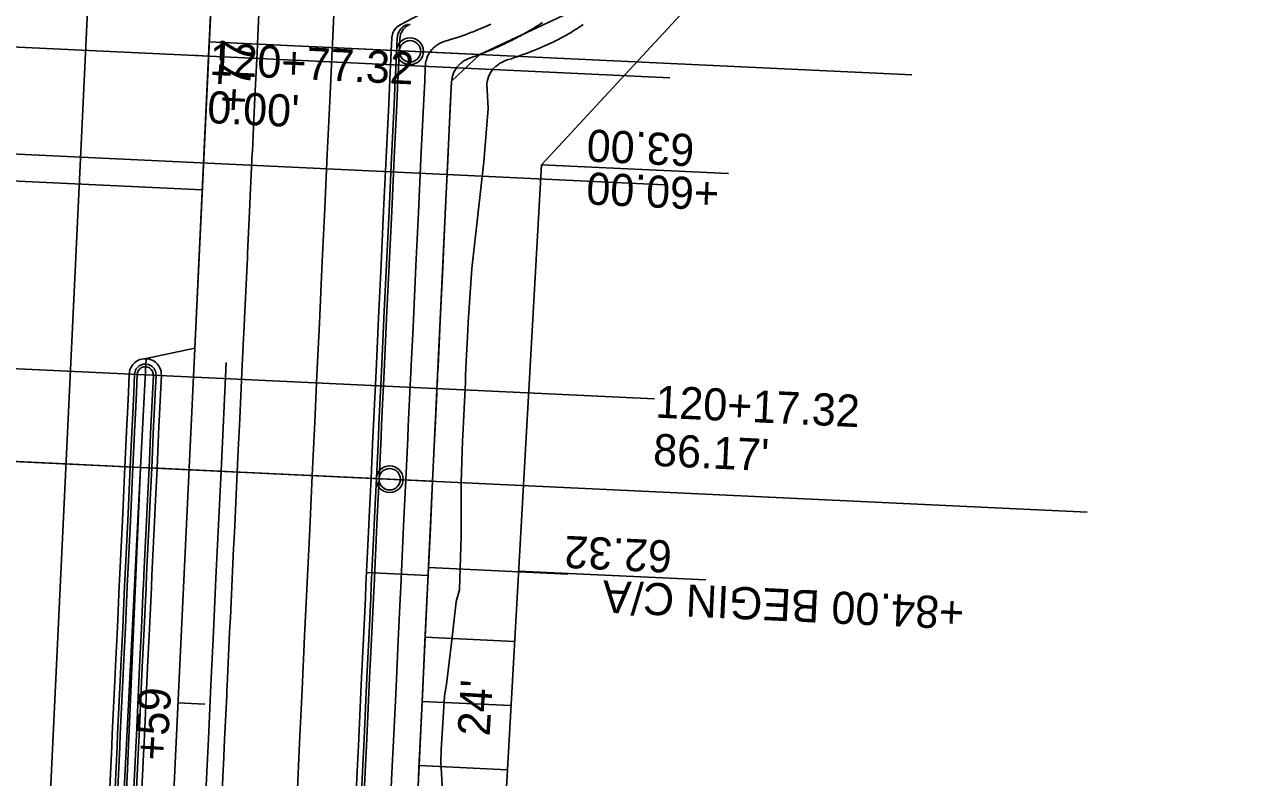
# Model space of a CAD drawing. Extents: x -70 to 701944, y -4 to 666871.
# Drawn here: x 668271.1 to 668502.1, y 655186.6 to 655327.1 of the extents above; entities that cross this region are included whole.
import ezdxf

# ---------------------------------------------------------------- set-up
doc = ezdxf.new("R2010")
doc.units = 0
for name, color, linetype in [('R_Detour', 7, 'Continuous'), ('R_Drive', 7, 'Continuous'), ('R_Horz Alg', 7, 'Continuous'), ('R_No Plot', 7, 'Continuous'), ('R_Proposed Const Limits', 7, 'Continuous'), ('R_Proposed Road', 7, 'Continuous'), ('R_ROW', 7, 'Continuous'), ('R_ROW Annot', 7, 'Continuous'), ('R_Striping', 7, 'Continuous'), ('R_Water', 7, 'Continuous'), ('T_Indications', 7, 'Continuous')]:
    doc.layers.add(name, color=color, linetype=linetype)

msp = doc.modelspace()

# ---------------------------------------------------------------- linework, layer by layer
at = {"layer": 'R_Detour'}
for p, q in [((668436.69, 655317.7), (668305.54, 655323.89)), ((668183.7, 655249.55), (668301.77, 655243.98)), ((668469.42, 655236.07), (668301.77, 655243.98))]:
    msp.add_line(p, q, dxfattribs=at)
at = {"layer": 'R_Drive'}
for p, q in [((668305.41, 655321.22), (668302.41, 655321.36)), ((668334.9, 655224.8), (668346.39, 655224.26)), ((668345.84, 655212.72), (668362.53, 655211.93)), ((668299.71, 655200.43), (668304.71, 655200.2)), ((668344.71, 655188.75), (668361.18, 655187.97))]:
    msp.add_line(p, q, dxfattribs=at)
at = {"layer": 'R_Horz Alg'}
msp.add_line((668254.91, 654251.16), (668327.61, 655791.56), dxfattribs=at)
msp.add_lwpolyline([(668294.77, 655244.31), (668308.76, 655243.65)], dxfattribs=at)
at = {"layer": 'R_No Plot'}
for p, q in [((668198.92, 655326.24), (668391.49, 655317.16)), ((668197.97, 655306.27), (668390.55, 655297.18)), ((668304.23, 655296.25), (668187.13, 655301.77)), ((668196.09, 655266.31), (668388.66, 655257.22)), ((668346.46, 655225.71), (668372.5, 655224.48)), ((668345.28, 655200.73), (668361.86, 655199.95))]:
    msp.add_line(p, q, dxfattribs=at)
for points in [[(668217.12, 655373.11), (668213.57, 655355.07), (668212.94, 655313.25), (668210.91, 655248.27), (668292.71, 655244.41), (668293.73, 655264.72), (668302.84, 655266.71), (668307.66, 655368.84)], [(668306.48, 655343.87), (668381.99, 655340.31), (668372.53, 655329.22), (668356.03, 655321.51), (668305.54, 655323.89)], [(668305.54, 655323.89), (668356.03, 655321.51), (668350.76, 655316.55), (668347.22, 655241.84), (668292.71, 655244.41), (668293.73, 655264.72), (668302.84, 655266.71)], [(668210.91, 655248.27), (668292.71, 655244.41), (668289.88, 655179.47), (668211.95, 655183.15)], [(668292.71, 655244.41), (668347.22, 655241.84), (668340.15, 655092), (668285.12, 655094.6)]]:
    msp.add_lwpolyline(points, close=True, dxfattribs=at)
for centre in [(668343.01, 655322.12), (668339.23, 655242.21)]:
    msp.add_circle(centre, 2.5, dxfattribs=at)
at = {"layer": 'R_Proposed Const Limits'}
msp.add_lwpolyline([(668349.21, 655181.68), (668348.79, 655189.43), (668348.79, 655189.45), (668348.82, 655191.7), (668349.44, 655201.69), (668349.89, 655204.36), (668349.9, 655204.45), (668350.77, 655211.63), (668351.63, 655219.29), (668351.65, 655219.39), (668352.23, 655221.58), (668352.57, 655231.57), (668352.57, 655234.26), (668352.57, 655234.35), (668352.57, 655241.58), (668352.8, 655249.39), (668352.92, 655251.58), (668352.98, 655252.9), (668353.12, 655255.42), (668353.25, 655257.94), (668353.31, 655258.89), (668353.37, 655260.47), (668353.39, 655261.57), (668353.43, 655263), (668353.78, 655270.05), (668353.86, 655271.56), (668354.56, 655281.53), (668355.69, 655291.49), (668356.82, 655301.45), (668357.62, 655311.42), (668357.37, 655316.01), (668357.41, 655316.47), (668357.51, 655316.92), (668357.65, 655317.36), (668357.84, 655317.79), (668358.07, 655318.2), (668358.34, 655318.59), (668358.53, 655318.81), (668358.66, 655318.95), (668358.99, 655319.27), (668359.01, 655319.29), (668359.39, 655319.6), (668359.57, 655319.72), (668359.81, 655319.87), (668360.25, 655320.11), (668360.33, 655320.15), (668360.7, 655320.32), (668361.16, 655320.49), (668361.38, 655320.56), (668361.93, 655320.73), (668362.54, 655320.94), (668362.76, 655321.01), (668363.21, 655321.17), (668363.59, 655321.3), (668364.34, 655321.58), (668364.53, 655321.65), (668365.37, 655321.97), (668365.91, 655322.18), (668366.11, 655322.26), (668366.76, 655322.53), (668367.31, 655322.76), (668367.45, 655322.82), (668367.76, 655322.95), (668368.12, 655323.11), (668368.32, 655323.2), (668368.33, 655323.2), (668368.98, 655323.5), (668369.1, 655323.56), (668369.13, 655323.57), (668369.84, 655323.9), (668370.17, 655324.07), (668370.47, 655324.21), (668370.52, 655324.24), (668371.14, 655324.56), (668371.22, 655324.6), (668371.71, 655324.86), (668371.9, 655324.97), (668372.2, 655325.13), (668372.28, 655325.17), (668372.62, 655325.37), (668372.96, 655325.57), (668373.26, 655325.76), (668373.3, 655325.78), (668374.32, 655326.44), (668374.54, 655326.58), (668375.33, 655327.12)], dxfattribs=at)
at = {"layer": 'R_Proposed Road'}
msp.add_line((668341.2, 655327.07), (668357.58, 655335.72), dxfattribs=at)
for points in [[(668336.55, 655259.68), (668336.62, 655261.26), (668336.67, 655262.36), (668336.74, 655263.79), (668337.07, 655270.84), (668337.15, 655272.34), (668337.62, 655282.33), (668338.09, 655292.32), (668338.56, 655302.31), (668339.03, 655312.3), (668339.25, 655316.87), (668339.27, 655317.33), (668339.29, 655317.78), (668339.31, 655318.23), (668339.33, 655318.66), (668339.35, 655319.08), (668339.37, 655319.48), (668339.38, 655319.72), (668339.39, 655319.86), (668339.4, 655320.2), (668339.4, 655320.21), (668339.42, 655320.54), (668339.43, 655320.67), (668339.43, 655320.84), (668339.45, 655321.1), (668339.45, 655321.14), (668339.46, 655321.32), (668339.47, 655321.51), (668339.47, 655321.59), (668339.48, 655321.79), (668339.49, 655322.03), (668339.49, 655322.11), (668339.5, 655322.29), (668339.51, 655322.44), (668339.52, 655322.75), (668339.53, 655322.83), (668339.54, 655323.19), (668339.56, 655323.43), (668339.56, 655323.52), (668339.57, 655323.81), (668339.59, 655324.07), (668339.59, 655324.14), (668339.6, 655324.28), (668339.6, 655324.46), (668339.61, 655324.56), (668339.61, 655324.56), (668339.64, 655324.88), (668339.65, 655324.95), (668339.66, 655324.96), (668339.75, 655325.32), (668339.81, 655325.5), (668339.87, 655325.66), (668339.89, 655325.69), (668340.07, 655326.03), (668340.1, 655326.07), (668340.3, 655326.34), (668340.4, 655326.45), (668340.57, 655326.62), (668340.62, 655326.67), (668340.87, 655326.87), (668341.2, 655327.07), (668341.55, 655327.25)], [(668337.56, 655259.63), (668337.63, 655261.21), (668337.68, 655262.31), (668337.75, 655263.74), (668338.08, 655270.79), (668338.15, 655272.3), (668338.63, 655282.29), (668339.1, 655292.27), (668339.57, 655302.26), (668340.04, 655312.25), (668340.26, 655316.82), (668340.28, 655317.28), (668340.3, 655317.73), (668340.32, 655318.18), (668340.34, 655318.61), (668340.36, 655319.03), (668340.38, 655319.43), (668340.39, 655319.67), (668340.4, 655319.81), (668340.41, 655320.15), (668340.41, 655320.17), (668340.43, 655320.49), (668340.43, 655320.62), (668340.44, 655320.79), (668340.45, 655321.05), (668340.46, 655321.09), (668340.47, 655321.27), (668340.47, 655321.46), (668340.48, 655321.54), (668340.49, 655321.75), (668340.5, 655321.98), (668340.5, 655322.06), (668340.51, 655322.24), (668340.52, 655322.39), (668340.53, 655322.7), (668340.54, 655322.78), (668340.55, 655323.14), (668340.56, 655323.38), (668340.57, 655323.47), (668340.58, 655323.76), (668340.6, 655324.02), (668340.6, 655324.09), (668340.61, 655324.23), (668340.61, 655324.41), (668340.62, 655324.51), (668340.62, 655324.51), (668340.65, 655324.84), (668340.66, 655324.9), (668340.66, 655324.91), (668340.75, 655325.28), (668340.82, 655325.45), (668340.88, 655325.61), (668340.9, 655325.64), (668341.08, 655325.98), (668341.11, 655326.02), (668341.31, 655326.29), (668341.41, 655326.41), (668341.58, 655326.58), (668341.63, 655326.62), (668341.88, 655326.82), (668342.21, 655327.02), (668342.56, 655327.21)], [(668338.06, 655259.61), (668338.13, 655261.19), (668338.18, 655262.28), (668338.25, 655263.72), (668338.58, 655270.77), (668338.65, 655272.27), (668339.12, 655282.26), (668339.6, 655292.25), (668340.07, 655302.24), (668340.54, 655312.23), (668340.75, 655316.8), (668340.78, 655317.25), (668340.8, 655317.71), (668340.82, 655318.15), (668340.84, 655318.59), (668340.86, 655319.01), (668340.88, 655319.41), (668340.89, 655319.65), (668340.9, 655319.79), (668340.91, 655320.13), (668340.91, 655320.14), (668340.93, 655320.47), (668340.93, 655320.6), (668340.94, 655320.76), (668340.95, 655321.03), (668340.96, 655321.07), (668340.96, 655321.25), (668340.97, 655321.44), (668340.98, 655321.52), (668340.99, 655321.72), (668341, 655321.95), (668341, 655322.04), (668341.01, 655322.22), (668341.02, 655322.37), (668341.03, 655322.68), (668341.04, 655322.76), (668341.05, 655323.12), (668341.06, 655323.35), (668341.07, 655323.45), (668341.08, 655323.74), (668341.09, 655324), (668341.1, 655324.07), (668341.1, 655324.21), (668341.11, 655324.38), (668341.12, 655324.49), (668341.12, 655324.49), (668341.15, 655324.81), (668341.16, 655324.88), (668341.16, 655324.89), (668341.25, 655325.25), (668341.32, 655325.43), (668341.38, 655325.59), (668341.4, 655325.62), (668341.58, 655325.96), (668341.61, 655326), (668341.81, 655326.27), (668341.91, 655326.38), (668342.08, 655326.55), (668342.13, 655326.6), (668342.38, 655326.8), (668342.71, 655327), (668343.06, 655327.18)], [(668343, 655258.43), (668343.12, 655260.95), (668343.18, 655262.05), (668343.24, 655263.48), (668343.58, 655270.53), (668343.65, 655272.04), (668344.12, 655282.03), (668344.59, 655292.02), (668345.06, 655302), (668345.53, 655311.99), (668345.75, 655316.56), (668345.77, 655317.02), (668345.79, 655317.47), (668345.81, 655317.92), (668345.83, 655318.35), (668345.85, 655318.77), (668345.87, 655319.17), (668345.88, 655319.41), (668345.89, 655319.55), (668345.93, 655319.89), (668345.93, 655319.91), (668345.99, 655320.23), (668346.02, 655320.36), (668346.06, 655320.52), (668346.14, 655320.78), (668346.16, 655320.82), (668346.22, 655321), (668346.3, 655321.19), (668346.34, 655321.27), (668346.43, 655321.47), (668346.56, 655321.69), (668346.61, 655321.78), (668346.72, 655321.95), (668346.82, 655322.09), (668347.05, 655322.39), (668347.12, 655322.47), (668347.45, 655322.82), (668347.71, 655323.04), (668347.82, 655323.13), (668348.21, 655323.4), (668348.63, 655323.64), (668348.76, 655323.7), (668349.06, 655323.84), (668349.52, 655323.99), (668349.82, 655324.07), (668349.83, 655324.08), (668350.77, 655324.36), (668350.95, 655324.41), (668350.99, 655324.42), (668351.99, 655324.75), (668352.45, 655324.9), (668352.86, 655325.04), (668352.93, 655325.07), (668353.79, 655325.38), (668353.89, 655325.42), (668354.55, 655325.67), (668354.82, 655325.77), (668355.22, 655325.93), (668355.32, 655325.97), (668355.79, 655326.16), (668356.26, 655326.36), (668356.67, 655326.54), (668356.74, 655326.57), (668358.13, 655327.2)], [(668348.04, 655259.14), (668348.12, 655260.72), (668348.17, 655261.81), (668348.24, 655263.24), (668348.57, 655270.29), (668348.64, 655271.8), (668349.11, 655281.79), (668349.59, 655291.78), (668350.06, 655301.77), (668350.53, 655311.76), (668350.74, 655316.32), (668350.79, 655316.78), (668350.87, 655317.23), (668351, 655317.67), (668351.16, 655318.1), (668351.37, 655318.51), (668351.61, 655318.9), (668351.77, 655319.13), (668351.88, 655319.27), (668352.17, 655319.6), (668352.19, 655319.61), (668352.53, 655319.92), (668352.68, 655320.05), (668352.89, 655320.2), (668353.28, 655320.44), (668353.35, 655320.48), (668353.69, 655320.65), (668354.12, 655320.82), (668354.32, 655320.89), (668354.83, 655321.07), (668355.4, 655321.27), (668355.61, 655321.35), (668356.03, 655321.51), (668356.38, 655321.64), (668357.08, 655321.92), (668357.26, 655321.99), (668358.04, 655322.32), (668358.54, 655322.53), (668358.73, 655322.61), (668359.34, 655322.88), (668359.85, 655323.11), (668359.99, 655323.17), (668360.27, 655323.31), (668360.6, 655323.46), (668360.8, 655323.56), (668360.8, 655323.56), (668361.41, 655323.86), (668361.53, 655323.91), (668361.55, 655323.93), (668362.22, 655324.26), (668362.54, 655324.43), (668362.82, 655324.57), (668362.87, 655324.6), (668363.47, 655324.92), (668363.55, 655324.96), (668364.02, 655325.22), (668364.21, 655325.33), (668364.5, 655325.49), (668364.58, 655325.54), (668364.92, 655325.73), (668365.27, 655325.94), (668365.58, 655326.12), (668365.63, 655326.15), (668366.69, 655326.79), (668366.93, 655326.94), (668367.77, 655327.48)], [(668286.95, 655184.61), (668287.32, 655192.33), (668287.32, 655192.35), (668287.42, 655194.6), (668287.9, 655204.59), (668288.02, 655207.28), (668288.03, 655207.37), (668288.37, 655214.58), (668288.73, 655222.26), (668288.73, 655222.36), (668288.84, 655224.57), (668289.31, 655234.56), (668289.44, 655237.24), (668289.44, 655237.33), (668289.78, 655244.55), (668290.15, 655252.35), (668290.25, 655254.54), (668290.32, 655255.85), (668290.43, 655258.38), (668290.6, 655261.85)], [(668287.95, 655184.57), (668288.32, 655192.29), (668288.32, 655192.3), (668288.42, 655194.56), (668288.89, 655204.54), (668289.02, 655207.23), (668289.03, 655207.32), (668289.37, 655214.53), (668289.73, 655222.21), (668289.73, 655222.31), (668289.84, 655224.52), (668290.31, 655234.51), (668290.44, 655237.2), (668290.44, 655237.28), (668290.78, 655244.5), (668291.15, 655252.3), (668291.25, 655254.49), (668291.31, 655255.81), (668291.43, 655258.33), (668291.6, 655261.84)], [(668288.45, 655184.54), (668288.82, 655192.26), (668288.82, 655192.28), (668288.92, 655194.53), (668289.39, 655204.52), (668289.52, 655207.21), (668289.53, 655207.3), (668289.87, 655214.51), (668290.23, 655222.19), (668290.23, 655222.29), (668290.34, 655224.5), (668290.81, 655234.49), (668290.94, 655237.17), (668290.94, 655237.26), (668291.28, 655244.48), (668291.65, 655252.28), (668291.75, 655254.46), (668291.81, 655255.78), (668291.93, 655258.31), (668292.1, 655261.79)], [(668291.45, 655184.4), (668291.81, 655192.12), (668291.81, 655192.14), (668291.92, 655194.39), (668292.39, 655204.38), (668292.52, 655207.06), (668292.52, 655207.16), (668292.86, 655214.37), (668293.22, 655222.04), (668293.23, 655222.14), (668293.33, 655224.36), (668293.81, 655234.35), (668293.93, 655237.03), (668293.94, 655237.12), (668294.28, 655244.33), (668294.65, 655252.14), (668294.75, 655254.32), (668294.81, 655255.64), (668294.93, 655258.16), (668295.09, 655261.65)], [(668291.95, 655184.38), (668292.31, 655192.1), (668292.31, 655192.11), (668292.42, 655194.37), (668292.89, 655204.36), (668293.02, 655207.04), (668293.02, 655207.14), (668293.36, 655214.34), (668293.72, 655222.02), (668293.73, 655222.12), (668293.83, 655224.33), (668294.3, 655234.32), (668294.43, 655237.01), (668294.44, 655237.1), (668294.78, 655244.31), (668295.14, 655252.11), (668295.25, 655254.3), (668295.31, 655255.62), (668295.43, 655258.14), (668295.59, 655261.66)], [(668292.95, 655184.33), (668293.31, 655192.05), (668293.31, 655192.07), (668293.42, 655194.32), (668293.89, 655204.31), (668294.02, 655206.99), (668294.02, 655207.09), (668294.36, 655214.3), (668294.72, 655221.97), (668294.73, 655222.07), (668294.83, 655224.29), (668295.3, 655234.27), (668295.43, 655236.96), (668295.43, 655237.05), (668295.78, 655244.26), (668296.14, 655252.07), (668296.25, 655254.25), (668296.31, 655255.57), (668296.43, 655258.09), (668296.59, 655261.57)], [(668332.9, 655182.44), (668333.27, 655190.16), (668333.27, 655190.18), (668333.37, 655192.43), (668333.84, 655202.42), (668333.97, 655205.11), (668333.98, 655205.2), (668334.32, 655212.41), (668334.68, 655220.09), (668334.68, 655220.19), (668334.79, 655222.4), (668335.26, 655232.39), (668335.39, 655235.08), (668335.39, 655235.16), (668335.73, 655242.38), (668336.1, 655250.18), (668336.2, 655252.37), (668336.26, 655253.68), (668336.38, 655256.21), (668336.5, 655258.73), (668336.55, 655259.68)], [(668333.9, 655182.4), (668334.27, 655190.12), (668334.27, 655190.13), (668334.37, 655192.39), (668334.84, 655202.38), (668334.97, 655205.06), (668334.97, 655205.16), (668335.32, 655212.36), (668335.68, 655220.04), (668335.68, 655220.14), (668335.79, 655222.35), (668336.26, 655232.34), (668336.38, 655235.03), (668336.39, 655235.12), (668336.73, 655242.33), (668337.1, 655250.13), (668337.2, 655252.32), (668337.26, 655253.64), (668337.38, 655256.16), (668337.5, 655258.69), (668337.56, 655259.63)], [(668334.4, 655182.37), (668334.76, 655190.09), (668334.77, 655190.11), (668334.87, 655192.36), (668335.34, 655202.35), (668335.47, 655205.04), (668335.47, 655205.13), (668335.81, 655212.34), (668336.18, 655220.02), (668336.18, 655220.12), (668336.29, 655222.33), (668336.76, 655232.32), (668336.88, 655235.01), (668336.89, 655235.09), (668337.23, 655242.31), (668337.6, 655250.11), (668337.7, 655252.3), (668337.76, 655253.61), (668337.88, 655256.14), (668338, 655258.66), (668338.06, 655259.61)], [(668339.39, 655182.14), (668339.76, 655189.86), (668339.76, 655189.87), (668339.87, 655192.13), (668340.34, 655202.12), (668340.46, 655204.8), (668340.47, 655204.9), (668340.81, 655212.1), (668341.17, 655219.78), (668341.18, 655219.88), (668341.28, 655222.09), (668341.75, 655232.08), (668341.88, 655234.77), (668341.88, 655234.86), (668342.22, 655242.07), (668342.59, 655249.87), (668342.69, 655252.06), (668342.76, 655253.38), (668342.88, 655255.9), (668343, 655258.43)], [(668344.39, 655181.9), (668344.75, 655189.62), (668344.75, 655189.64), (668344.86, 655191.89), (668345.33, 655201.88), (668345.46, 655204.56), (668345.46, 655204.66), (668345.8, 655211.87), (668346.17, 655219.55), (668346.17, 655219.65), (668346.27, 655221.86), (668346.75, 655231.85), (668346.87, 655234.53), (668346.88, 655234.62), (668347.22, 655241.84), (668347.59, 655249.64), (668347.69, 655251.82), (668347.75, 655253.14), (668347.87, 655255.67), (668347.99, 655258.19), (668348.04, 655259.14)]]:
    msp.add_lwpolyline(points, dxfattribs=at)
for centre, radius, start, end in [((668342.61, 655324.42), 3, 117.8545, 177.2979), ((668293.59, 655261.72), 3, 357.0332, 177.5626), ((668293.59, 655261.72), 2, 357.0332, 177.5626), ((668293.59, 655261.72), 1.5, 357.0332, 177.5626)]:
    msp.add_arc(centre, radius, start, end, dxfattribs=at)
at = {"layer": 'R_ROW'}
msp.add_lwpolyline([(668379.35, 655858.1), (668375.98, 655777.07), (668370.36, 655679.23), (668386.89, 655520.28), (668407.12, 655376.16), (668401.28, 655337.39), (668367.53, 655300.94), (668336.13, 654741.8), (668319.02, 654252.06), (668346.25, 654066.79), (668364.92, 653986.53), (668401.01, 653983.18), (668425.78, 653872.16), (668398.63, 653868.03), (668433.79, 653730.98), (668450.99, 653639.16), (668466.96, 653535.35), (668502.13, 653505.82)], dxfattribs=at)
at = {"layer": 'R_ROW Annot'}
for points in [[(668367.53, 655300.94), (668402.49, 655299.29)], [(668363.27, 655225.06), (668398.23, 655223.41)]]:
    msp.add_lwpolyline(points, dxfattribs=at)
at = {"layer": 'R_Striping'}
msp.add_line((668271.25, 655085.25), (668286.33, 655404.86), dxfattribs=at)
for points in [[(668325.56, 655260.19), (668325.69, 655262.87), (668326.09, 655271.35), (668326.16, 655272.86), (668326.63, 655282.85), (668327.1, 655292.84), (668327.57, 655302.83), (668328.04, 655312.82), (668328.49, 655322.31), (668332.27, 655402.73), (668332.27, 655402.92)], [(668299.16, 655062.11), (668299.24, 655063.89), (668299.71, 655073.88), (668300.18, 655083.87), (668300.66, 655093.86), (668301.13, 655103.84), (668301.6, 655113.83), (668302.07, 655123.82), (668302.54, 655133.81), (668303.01, 655143.8), (668303.48, 655153.79), (668303.96, 655163.78), (668304.43, 655173.77), (668304.9, 655183.75), (668305.37, 655193.74), (668305.84, 655203.73), (668306.31, 655213.72), (668306.78, 655223.71), (668307.26, 655233.7), (668307.73, 655243.69), (668308.69, 655264.01)], [(668321.92, 655182.97), (668322.39, 655192.96), (668322.86, 655202.95), (668323.33, 655212.93), (668323.8, 655222.92), (668324.28, 655232.91), (668324.75, 655242.9), (668325.22, 655252.89), (668325.56, 655260.2)]]:
    msp.add_lwpolyline(points, dxfattribs=at)
at = {"layer": 'R_Water'}
for centre in [(668343.01, 655322.12), (668339.23, 655242.21)]:
    msp.add_circle(centre, 2, dxfattribs=at)
at = {"layer": 'T_Indications'}
msp.add_lwpolyline([(668307.93, 655183.62), (668308.14, 655188.05), (668308.18, 655188.89), (668308.4, 655193.61), (668308.79, 655201.8), (668308.82, 655202.62), (668308.87, 655203.6), (668309.34, 655213.59), (668309.43, 655215.56), (668309.47, 655216.35), (668309.81, 655223.58), (668310.08, 655229.31), (668310.12, 655230.08), (668310.28, 655233.57), (668310.76, 655243.56), (668311.01, 655248.91), (668311.05, 655249.82), (668311.23, 655253.55), (668311.7, 655263.53), (668311.93, 655268.51), (668311.98, 655269.55), (668312.17, 655273.52), (668312.59, 655282.34), (668312.64, 655283.51), (668312.68, 655284.38), (668313.11, 655293.5), (668313.19, 655295.13), (668313.57, 655303.09), (668313.58, 655303.49), (668313.79, 655307.92), (668314.06, 655313.48), (668314.4, 655320.71), (668314.45, 655321.8), (668314.53, 655323.47), (668315, 655333.46)], dxfattribs=at)

# ---------------------------------------------------------------- texts
at = {"layer": 'R_Drive'}
for s, p in [('+77', (668312.85, 655310.58)), ('+59', (668297.62, 655189.55)), ("24'", (668357.87, 655194.12))]:
    msp.add_text(s, height=6, rotation=86.5585, dxfattribs=at).set_placement(p)
at = {"layer": 'R_No Plot'}
for s, height, rotation, p in [('120+77.32 ', 6, 357.2978, (668305.48, 655317.72)), ('+', 0.1, 87.2978, (668305.45, 655320.85)), ('+', 0.1, 87.2978, (668305.45, 655320.85)), ("0.00' ", 6, 357.2978, (668305.06, 655308.73)), ('120+17.32 ', 6, 357.2978, (668388.73, 655253.72)), ("86.17' ", 6, 357.2978, (668388.31, 655244.73)), ('+', 0.1, 87.2978, (668299.88, 655202.98))]:
    msp.add_text(s, height=height, rotation=rotation, dxfattribs=at).set_placement(p)
at = {"layer": 'R_ROW Annot'}
for s, p in [('63.00', (668396.23, 655306.6)), ('+60.00', (668400.85, 655298.37)), ('62.32', (668392.04, 655230.71)), ('+84.00 BEGIN C/A', (668446.6, 655220.13))]:
    msp.add_text(s, height=6, rotation=177.2978, dxfattribs=at).set_placement(p)

doc.saveas('drawing.dxf')
